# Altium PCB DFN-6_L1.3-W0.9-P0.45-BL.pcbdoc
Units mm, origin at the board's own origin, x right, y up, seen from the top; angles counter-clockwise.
Board outline 14.29 x 14.27 mm, 2 copper layers (Top Layer, Bottom Layer), stack 0 mm thick; 1 components, 0 nets, 6 pads, 0 vias.
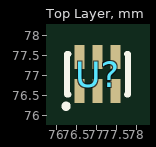
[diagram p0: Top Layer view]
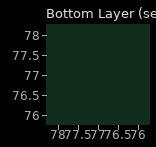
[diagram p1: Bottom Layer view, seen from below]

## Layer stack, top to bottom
Top Layer: signal copper (thickness not stored)
Bottom Layer: signal copper (thickness not stored)

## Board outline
84.142,69.85 69.85,69.85 69.85,84.115 84.142,84.115

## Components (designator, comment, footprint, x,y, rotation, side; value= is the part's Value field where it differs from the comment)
U? "" DFN-6_L1.3-W0.9-P0.45-BL 77.03,77.04 r0 top

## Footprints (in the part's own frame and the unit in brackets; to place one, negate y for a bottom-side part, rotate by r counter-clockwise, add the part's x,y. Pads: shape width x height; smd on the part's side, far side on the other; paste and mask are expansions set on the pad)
DFN-6_L1.3-W0.9-P0.45-BL [mm]
  rect 0.25x0.6 smd paste+0 mask+0.04: 1(-0.45,-0.425) 2(0,-0.425) 3(0.45,-0.425) 4(0.45,0.425) 5(0,0.425) 6(-0.45,0.425)
  silkscreen extent -0.83,-0.84 0.76,0.51

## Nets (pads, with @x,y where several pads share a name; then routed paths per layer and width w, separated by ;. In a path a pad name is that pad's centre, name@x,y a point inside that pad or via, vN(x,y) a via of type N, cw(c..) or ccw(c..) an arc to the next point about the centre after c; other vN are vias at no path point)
pads on no net: U?.1 U?.2 U?.3 U?.4 U?.5 U?.6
